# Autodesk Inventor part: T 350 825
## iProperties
Company: Mayer & Müller AG Schaltgeräte
Created: 2005-12
Part Number: T 350 825
Material: E-Cu F20
Document SubType Name: Sheet Metal
Designer: I.Baliuc
Manufacturer: Standard
Standards Organization: Custom
Description: Stromband
Density: 8.94 g/cm^3
Sheet Metal Rule: Standard
HalbzeugNorm: DIN 1791
Zweck: für Hauptkontakt
Abmessung: Band 78 x 0,1
Author: T.Messerschmitt
Revision Number: 350825
Comments: Schalter im geschlossenen Zustand
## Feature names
1. Bohrung_Ø10.5 [Hole]
2. Extrusion1
3. Spiegeln1 [Mirror]
4. Bohrung_Ø6.5 [Hole]
5. Grobblech1
6. Biegung1
7. ExtrusionAbwicklung2
